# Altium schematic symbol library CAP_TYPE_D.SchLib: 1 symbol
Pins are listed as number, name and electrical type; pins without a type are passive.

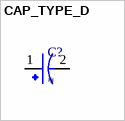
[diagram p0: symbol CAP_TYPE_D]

## CAP_TYPE_D
designator C?
MP: 25TQC15MV
footprint CAP_TYPE_D
pins: 1, 2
